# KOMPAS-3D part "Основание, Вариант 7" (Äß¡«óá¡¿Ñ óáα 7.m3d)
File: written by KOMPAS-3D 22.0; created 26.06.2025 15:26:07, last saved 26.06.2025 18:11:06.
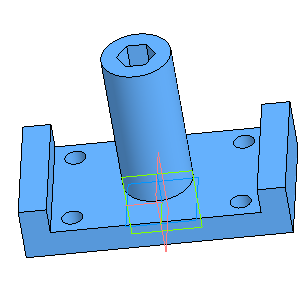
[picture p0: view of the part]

Document properties: Автор: Helen; Полное имя файла: D:\MY\WORK\MPEI\ППЭ_2025-2026\Варианты\Вар 7 СБ\Основание вар 7.m3d

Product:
- Body: Тело 1
    Масса: 5.199473
- Part/product: Основание  | designation Вариант 7
    Масса: 4.690027

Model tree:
1. Эскиз:1
2. Элемент выдавливания:1
     Расстояние 1 = 20
3. Эскиз:3  (with: Элемент выдавливания:1)
4. Элемент выдавливания:3
     Расстояние 2 = 20
5. Массив по сетке:1  (with: Элемент выдавливания:3, Эскиз:3, Элемент выдавливания:1)  (4 pattern instances)
     Шаг 1 = 120; Угол раствора = 90; Шаг 2 = 70
6. Эскиз:4  (with: Элемент выдавливания:1)
7. Элемент выдавливания:4
     Расстояние 1 = 110
8. Эскиз:6  (with: Элемент выдавливания:1)
9. Элемент выдавливания:6
     Расстояние 1 = 20
10. Зеркальный массив:1
11. Экземпляр ( 1 )
12. Экземпляр ( 2 )  (with: Элемент выдавливания:6)
13. Эскиз:7  (with: Элемент выдавливания:4)
14. Элемент выдавливания:7
     Расстояние 2 = 130

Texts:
  Вариант 7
